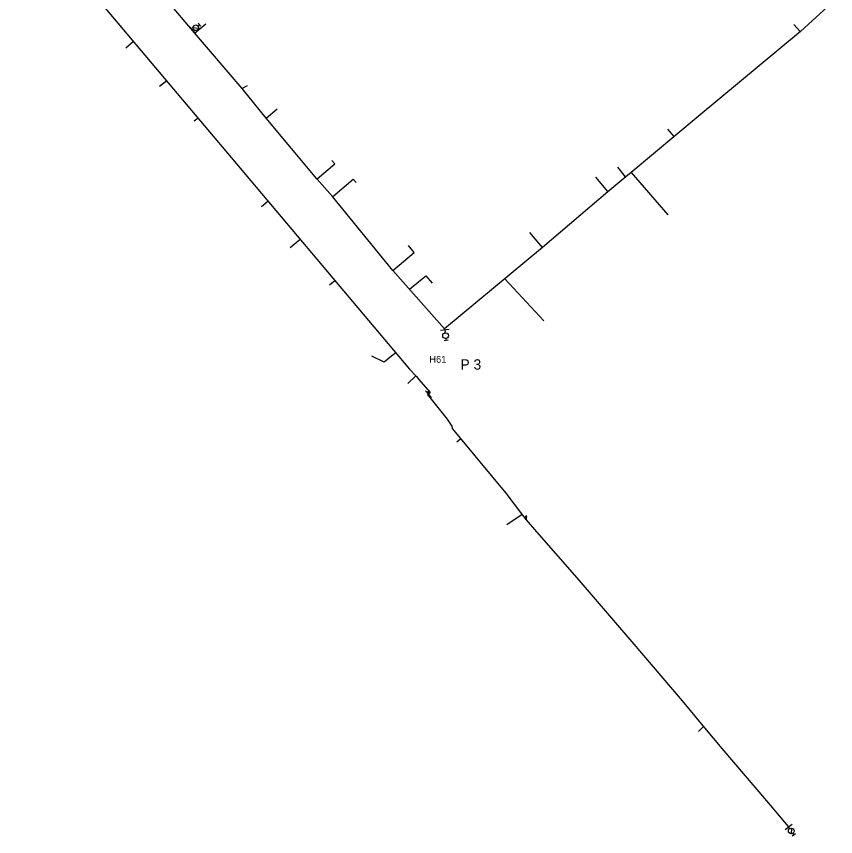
# Model space of a CAD drawing. Extents: x -548873 to -538270, y -1201997 to -1192514.
# Drawn here: x -548135.1 to -547897.8, y -1196782.3 to -1196544.8 of the extents above; entities that cross this region are included whole.
import ezdxf

# ---------------------------------------------------------------- set-up
doc = ezdxf.new("R2010")
doc.units = 0
for name, color, linetype in [('KN_HRAN_STÁTNÍ', 7, 'Continuous'), ('KN_PARC_Č', 7, 'Continuous'), ('KN_VKP_HRAN_SPORNÁ', 7, 'Continuous'), ('PK_PARC_Čv', 7, 'Continuous'), ('Vrstva 29', 7, 'Continuous'), ('Vrstva 39', 7, 'Continuous')]:
    doc.layers.add(name, color=color, linetype=linetype)

# ---------------------------------------------------------------- blocks, each defined once
blk = doc.blocks.new('160')
at = {"layer": 'KN_HRAN_STÁTNÍ'}
blk.add_circle((0, 0), 0.0458, dxfattribs=at)
blk = doc.blocks.new('147')
at = {"layer": 'KN_HRAN_STÁTNÍ'}
blk.add_line((0, 1.27), (0, -1.27), dxfattribs=at)
blk = doc.blocks.new('133')
at = {"layer": 'KN_HRAN_STÁTNÍ'}
for p, q in [((0.28, 0), (0, 0)), ((0.54, 0.58), (1.7, -0.58)), ((1.94, 0), (2.52, 0)), ((2.52, 0.58), (2.52, -0.58))]:
    blk.add_line(p, q, dxfattribs=at)
blk.add_circle((1.11, 0), 0.825, dxfattribs=at)
blk = doc.blocks.new('132')
at = {"layer": 'KN_HRAN_STÁTNÍ'}
for p, q in [((0.3, 0), (0, 0)), ((1.96, 0), (2.52, 0)), ((2.52, 0.58), (2.52, -0.58))]:
    blk.add_line(p, q, dxfattribs=at)
blk.add_circle((1.13, 0.01), 0.825, dxfattribs=at)
blk = doc.blocks.new('150')
at = {"layer": 'KN_HRAN_STÁTNÍ'}
blk.add_line((0, 1.27), (0, -1.27), dxfattribs=at)
blk = doc.blocks.new('123')
at = {"layer": 'KN_HRAN_STÁTNÍ'}
for p, q in [((-0.26, 0.96), (0.26, 0.96)), ((-0.19, 1.13), (0.19, 0.79)), ((-0.19, 0.79), (0, 0.96)), ((0, 1.22), (0, 0.96)), ((0, 0.96), (0.19, 1.13)), ((0, 0.96), (0, 0))]:
    blk.add_line(p, q, dxfattribs=at)
blk = doc.blocks.new('128')
at = {"layer": 'KN_HRAN_STÁTNÍ'}
for p, q in [((-0.19, 1.06), (-0.43, 1.15)), ((-0.36, 0.84), (-0.19, 1.06)), ((-0.19, 1.06), (-0.02, 1.25)), ((-0.19, 1.06), (0, 0)), ((0.05, 0.95), (-0.19, 1.06)), ((-0.1, 1), (0.41, 0.91)), ((-0.07, 0.82), (0.17, 0.96)), ((0.17, 0.96), (-0.02, 1.13)), ((0.17, 0.96), (0, 0)), ((0.19, 1.21), (0.17, 0.96)), ((0.17, 0.96), (0.38, 1.08)), ((0.36, 0.77), (0.17, 0.96))]:
    blk.add_line(p, q, dxfattribs=at)

msp = doc.modelspace()

# ---------------------------------------------------------------- linework, layer by layer
at = {"layer": 'KN_PARC_Č'}
for points in [[(-548083.512, -1196549.601), (-548080.227, -1196546.888)], [(-547908.031, -1196549.172), (-547909.904, -1196547.122)], [(-548101.148, -1196552.013), (-548103.394, -1196553.93)], [(-548091.517, -1196563.455), (-548093.68, -1196565.08)], [(-548069.746, -1196565.645), (-548068.194, -1196564.772)], [(-548062.744, -1196574.225), (-548059.549, -1196571.53)], [(-548082.438, -1196574.241), (-548083.62, -1196575.16)], [(-547944.567, -1196579.593), (-547946.384, -1196577.45)], [(-548048.014, -1196591.861), (-548042.876, -1196587.491), (-548043.703, -1196586.506)], [(-547958.609, -1196591.284), (-547960.915, -1196588.486)], [(-547957.045, -1196589.983), (-547946.4, -1196602.25)], [(-548043.475, -1196596.905), (-548037.534, -1196591.877), (-548036.684, -1196592.854)], [(-547963.767, -1196595.501), (-547967.214, -1196591.343)], [(-548062.208, -1196598.276), (-548064.088, -1196599.915)], [(-548052.86, -1196609.382), (-548055.792, -1196611.784)], [(-547982.671, -1196611.707), (-547986.319, -1196607.339)], [(-548026.04, -1196618.376), (-548019.846, -1196613.115), (-548021.478, -1196611.171)], [(-548021.234, -1196623.795), (-548016.459, -1196619.914), (-548014.646, -1196622.036)], [(-547993.62, -1196620.8), (-547982.33, -1196632.91)], [(-548042.803, -1196621.331), (-548044.44, -1196622.65)], [(-548025.222, -1196642.217), (-548026.405, -1196643.156), (-548028.591, -1196644.91), (-548032.135, -1196643.184)], [(-548019.391, -1196648.891), (-548021.657, -1196651.069)], [(-548006.334, -1196667.143), (-548007.501, -1196668.116)], [(-547988.622, -1196689.014), (-547993.054, -1196692.08)], [(-547936.089, -1196750.439), (-547937.483, -1196751.874)]]:
    msp.add_lwpolyline(points, dxfattribs=at)
at = {"layer": 'KN_VKP_HRAN_SPORNÁ'}
for points in [[(-547897.793, -1196539.827), (-547907.95, -1196549.104), (-547937.619, -1196573.808), (-547957.046, -1196589.983), (-547958.561, -1196591.245), (-547963.814, -1196595.539), (-547982.701, -1196611.732), (-548011.05, -1196635.276), (-548026.085, -1196618.326), (-548043.48, -1196596.899), (-548048.066, -1196591.803), (-548062.754, -1196574.213), (-548069.718, -1196565.679), (-548083.537, -1196549.571), (-548097.468, -1196532.936), (-548113.673, -1196513.39), (-548122.436, -1196503.246), (-548134.571, -1196512.211)], [(-548135.09, -1196512.598), (-548127.57, -1196522.27), (-548126.3, -1196523.78), (-548125.42, -1196523.08), (-548123.91, -1196524.97), (-548068.725, -1196590.533), (-548021.197, -1196647), (-548019.21, -1196649.08), (-548018.54, -1196649.91), (-548015.26, -1196653.73), (-548015.35, -1196653.82), (-548015.54, -1196653.98), (-548015.72, -1196654.16)], [(-548015.72, -1196654.16), (-548015.98, -1196654.35), (-548015.68, -1196654.68)], [(-548015.68, -1196654.68), (-548010.28, -1196661.46), (-548008.96, -1196663.5), (-548008.85, -1196664.1), (-548006.524, -1196666.913), (-547993.33, -1196682.87), (-547988.465, -1196689.219), (-547987.469, -1196690.561)], [(-547987.469, -1196690.561), (-547984.41, -1196694.07), (-547972.76, -1196707.4), (-547956.78, -1196725.89), (-547942.23, -1196743.06), (-547935.736, -1196750.863), (-547930.77, -1196756.83), (-547917.82, -1196772.03), (-547911.519, -1196779.448)]]:
    msp.add_lwpolyline(points, dxfattribs=at)
at = {"layer": 'PK_PARC_Čv'}
for points in [[(-548084.104, -1196548.893), (-548083.98, -1196548.79)], [(-548011.05, -1196635.276), (-548010.95, -1196635.59), (-548010.9, -1196636.13)], [(-547911.519, -1196779.448), (-547911.39, -1196779.6), (-547911.26, -1196779.8)]]:
    msp.add_lwpolyline(points, dxfattribs=at)

# ---------------------------------------------------------------- block references
for name, p, xscale, yscale, rotation in [('133', (-548083.98, -1196548.79), 1.0000000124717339, 1.0000000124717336, 40.00000131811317), ('150', (-548084.039, -1196548.839), 1.0000000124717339, 1.0000000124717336, 40.00000131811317), ('150', (-548010.95, -1196635.59), 1.0011217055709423, 1.0011217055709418, -83.41739016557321), ('132', (-548010.9, -1196636.13), 1.0011217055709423, 1.0011217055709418, -83.41739016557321), ('150', (-547911.39, -1196779.6), 0.9999999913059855, 0.9999999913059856, -52.999998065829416), ('133', (-547911.26, -1196779.8), 0.9999999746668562, 0.999999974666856, -55.999999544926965)]:
    msp.add_blockref(name, p, dxfattribs=dict(at, xscale=xscale, yscale=yscale, rotation=rotation))
at = {"layer": 'Vrstva 29'}
for name, p, xscale, yscale, rotation in [('147', (-548015.72, -1196654.16), 1.0000000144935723, 1.0000000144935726, 40.99999910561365), ('160', (-548015.68, -1196654.68), 1.0000000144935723, 1.0000000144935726, 130.99999910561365), ('160', (-547987.469, -1196690.561), 1.000000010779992, 1.0000000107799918, 128.99999891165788), ('160', (-547911.519, -1196779.448), 1.0000000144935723, 1.0000000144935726, 130.99999910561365)]:
    msp.add_blockref(name, p, dxfattribs=dict(at, xscale=xscale, yscale=yscale, rotation=rotation))
at = {"layer": 'Vrstva 39'}
for name, p in [('128', (-548015.68, -1196654.68)), ('123', (-547987.469, -1196690.561))]:
    msp.add_blockref(name, p, dxfattribs=at)

# ---------------------------------------------------------------- texts
at = {"layer": 'PK_PARC_Čv'}
for s, height, p in [('H61', 2, (-548015.46, -1196645.11)), ('P 3', 3, (-548006.47, -1196647.09))]:
    msp.add_text(s, height=height, dxfattribs=at).set_placement(p)

doc.saveas('drawing.dxf')
